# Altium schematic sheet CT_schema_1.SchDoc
size 604 x 452 mm
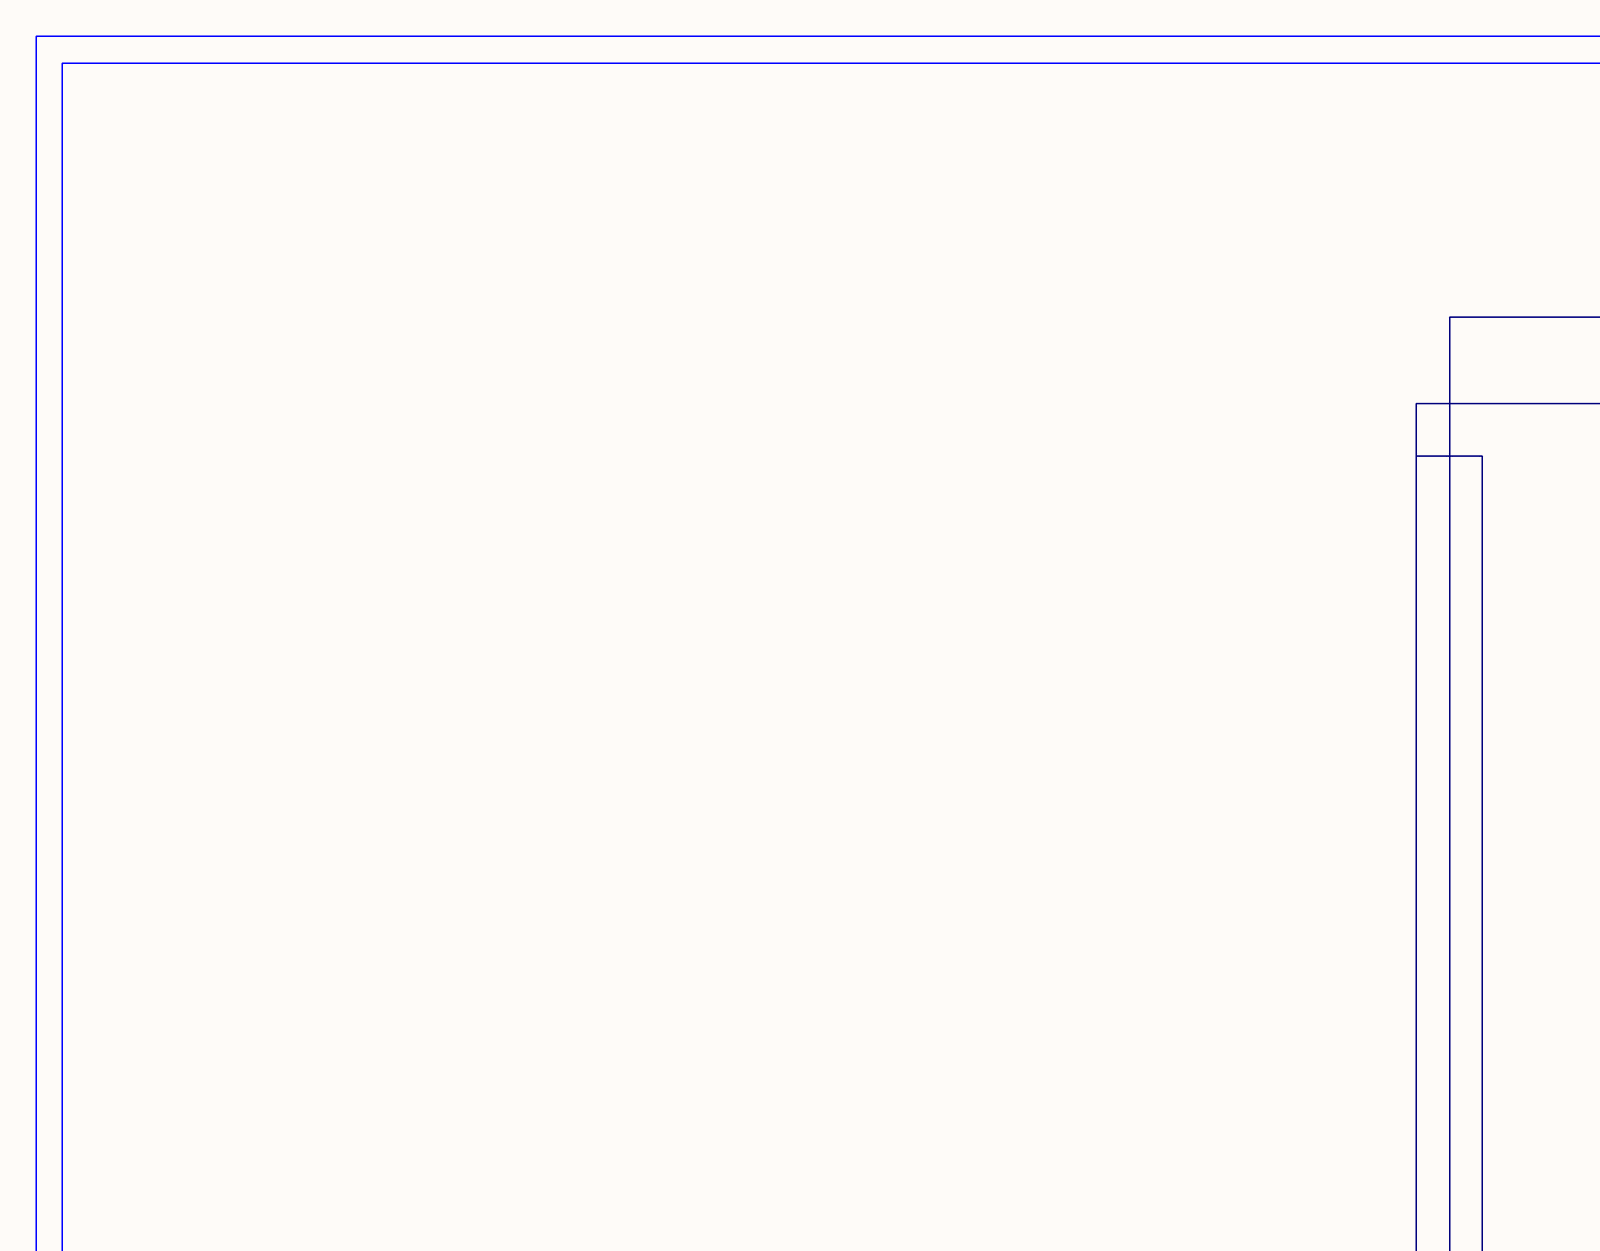
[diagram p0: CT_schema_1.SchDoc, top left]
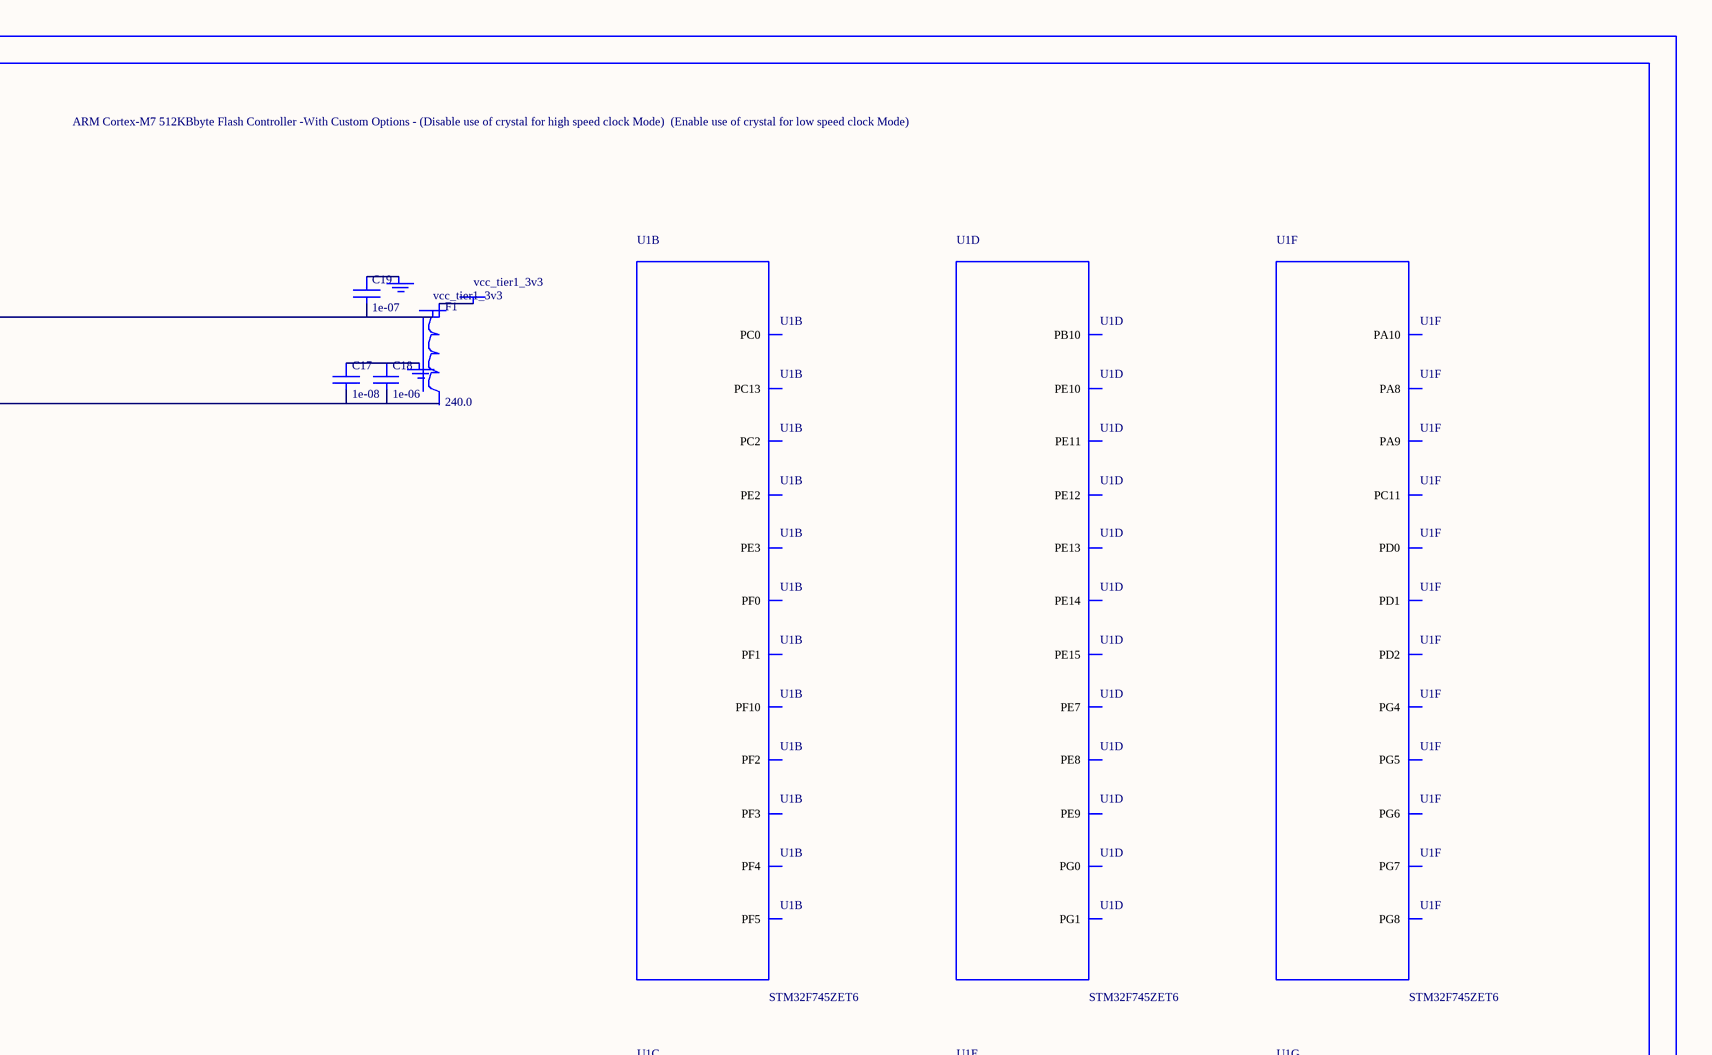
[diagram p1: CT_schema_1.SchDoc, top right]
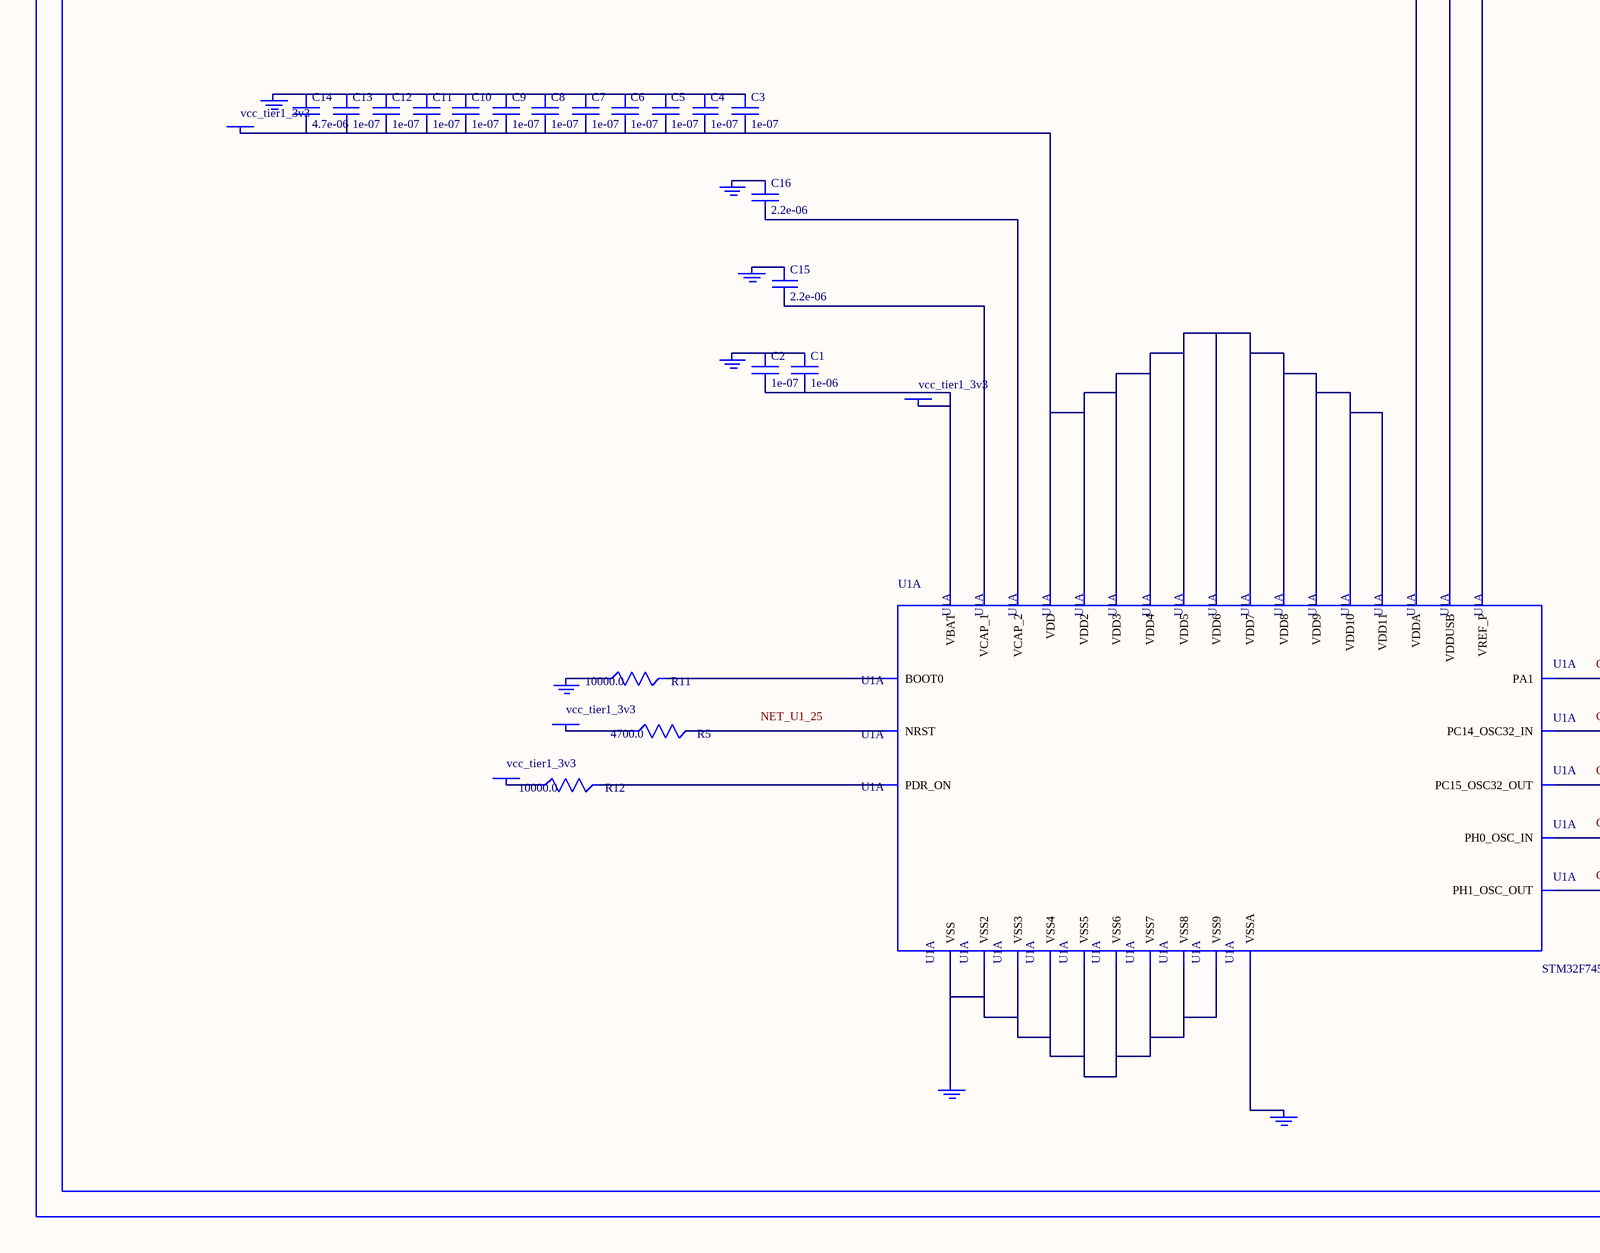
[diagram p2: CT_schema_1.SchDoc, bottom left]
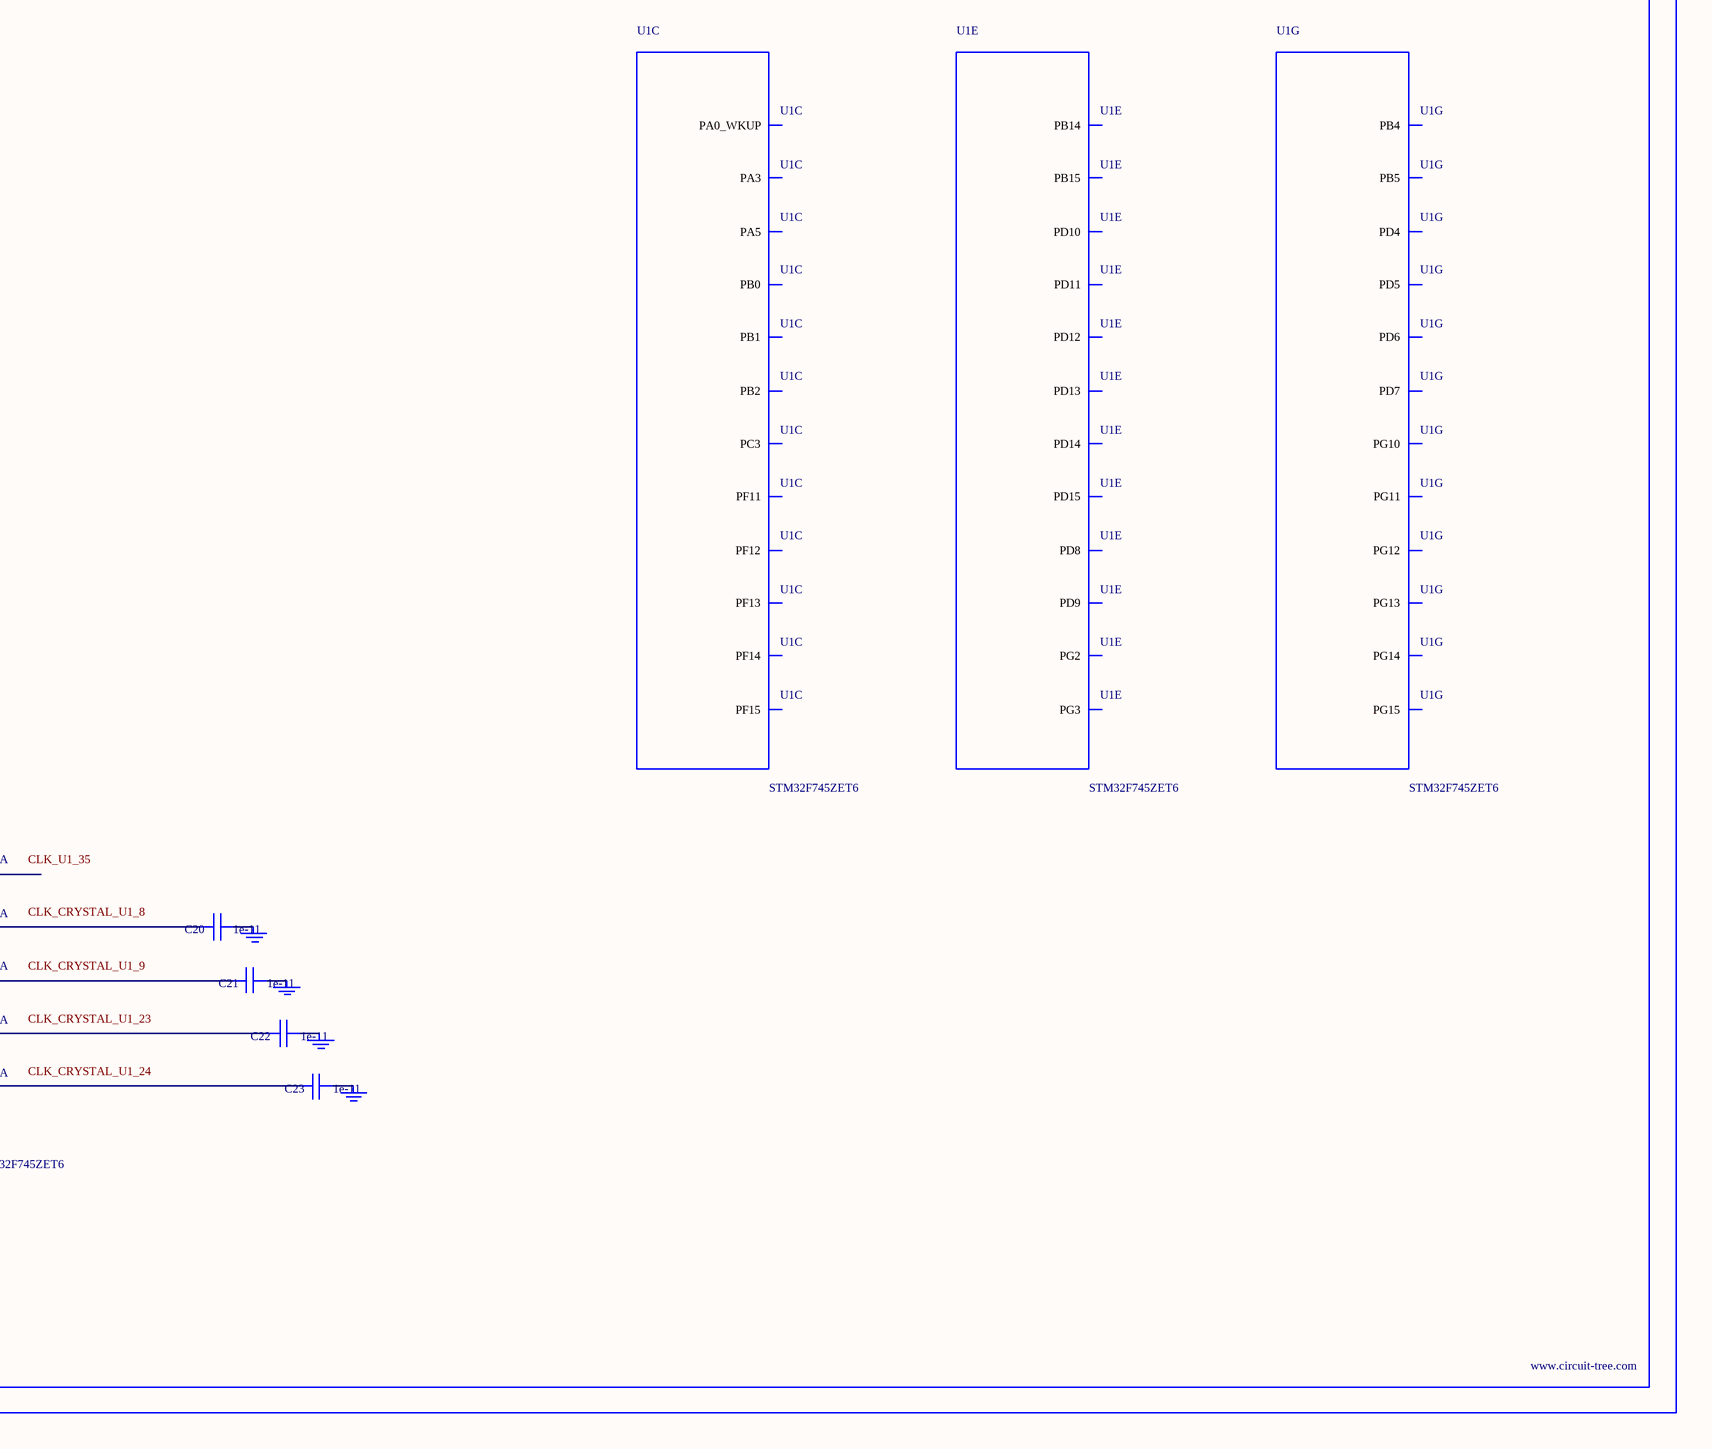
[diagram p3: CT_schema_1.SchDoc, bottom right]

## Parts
BORDER0  (no value)
C1  1e-06  [C0603]
C2  1e-07  [C0603]
C3  1e-07  [C0603]
C4  1e-07  [C0603]
C5  1e-07  [C0603]
C6  1e-07  [C0603]
C7  1e-07  [C0603]
C8  1e-07  [C0603]
C9  1e-07  [C0603]
C10  1e-07  [C0603]
C11  1e-07  [C0603]
C12  1e-07  [C0603]
C13  1e-07  [C0603]
C14  4.7e-06  [C0603]
C15  2.2e-06  [C0603]
C16  2.2e-06  [C0603]
C17  1e-08  [C0603]
C18  1e-06  [C0603]
C19  1e-07  [C0603]
C20  1e-11  [C0402]
C21  1e-11  [C0402]
C22  1e-11  [C0402]
C23  1e-11  [C0402]
F1  240.0  [L0603]
GND_INSTANCE_0_0  (no value)
GND_INSTANCE_0_1  (no value)
GND_INSTANCE_0_2  (no value)
GND_INSTANCE_0_3  (no value)
GND_INSTANCE_0_4  (no value)
GND_INSTANCE_0_5  (no value)
GND_INSTANCE_0_6  (no value)
GND_INSTANCE_0_7  (no value)
GND_INSTANCE_0_8  (no value)
GND_INSTANCE_0_9  (no value)
GND_INSTANCE_0_10  (no value)
GND_INSTANCE_0_11  (no value)
GND_INSTANCE_0_12  (no value)
POWER_INSTANCE_0_0  vcc_tier1_3v3
POWER_INSTANCE_0_1  vcc_tier1_3v3
POWER_INSTANCE_0_2  vcc_tier1_3v3
POWER_INSTANCE_0_3  vcc_tier1_3v3
POWER_INSTANCE_0_4  vcc_tier1_3v3
POWER_INSTANCE_0_5  vcc_tier1_3v3
R5  4700.0  [R0603]
R11  10000.0  [R0603]
R12  10000.0  [R0603]
U1  STM32F745ZET6  [LQFP144]  (parts A,B,C,D,E,F,G of 12)

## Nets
NetC1_1: C1.1 C2.1 GND_INSTANCE_0_0.0(GND)
NetC1_2: C1.2 C2.2 POWER_INSTANCE_0_0.0(PWR) U1.6(VBAT)
NetC3_1: C3.1 C4.1 C5.1 C6.1 C7.1 C8.1 C9.1 C10.1 C11.1 C12.1 C13.1 C14.1 GND_INSTANCE_0_3.0(GND)
NetC3_2: C3.2 C4.2 C5.2 C6.2 C7.2 C8.2 C9.2 C10.2 C11.2 C12.2 C13.2 C14.2 POWER_INSTANCE_0_1.0(PWR) U1.17(VDD) U1.30(VDD2) U1.39(VDD3) U1.52(VDD4) U1.62(VDD5) U1.72(VDD6) U1.84(VDD7) U1.108(VDD8) U1.121(VDD9) U1.131(VDD10) U1.144(VDD11)
NetC15_1: C15.1 GND_INSTANCE_0_8.0(GND)
NetC15_2: C15.2 U1.71(VCAP_1)
NetC16_1: C16.1 GND_INSTANCE_0_10.0(GND)
NetC16_2: C16.2 U1.106(VCAP_2)
NetC17_1: C17.1 C18.1 GND_INSTANCE_0_7.0(GND)
NetC17_2: C17.2 C18.2 U1.32(VREF_P) U1.33(VDDA)
NetC19_1: C19.1 GND_INSTANCE_0_9.0(GND)
NetC19_2: C19.2 POWER_INSTANCE_0_3.0(PWR) U1.95(VDDUSB)
NetC20_1: C20.1 GND_INSTANCE_0_1.0(GND)
NetC20_2: C20.2 U1.8(PC14_OSC32_IN)
NetC21_1: C21.1 GND_INSTANCE_0_2.0(GND)
NetC21_2: C21.2 U1.9(PC15_OSC32_OUT)
NetC22_1: C22.1 GND_INSTANCE_0_4.0(GND)
NetC22_2: C22.2 U1.23(PH0_OSC_IN)
NetC23_1: C23.1 GND_INSTANCE_0_5.0(GND)
NetC23_2: C23.2 U1.24(PH1_OSC_OUT)
NetF1_1: F1.1 POWER_INSTANCE_0_2.0(PWR)
NetGND_INSTANCE_0_6_0: GND_INSTANCE_0_6.0(GND) U1.31(VSSA)
NetGND_INSTANCE_0_11_0: GND_INSTANCE_0_11.0(GND) R11.1
NetGND_INSTANCE_0_12_0: GND_INSTANCE_0_12.0(GND) U1.16(VSS) U1.38(VSS2) U1.51(VSS3) U1.61(VSS4) U1.83(VSS5) U1.94(VSS6) U1.107(VSS7) U1.120(VSS8) U1.130(VSS9)
NetPOWER_INSTANCE_0_4_0: POWER_INSTANCE_0_4.0(PWR) R12.1
NetPOWER_INSTANCE_0_5_0: POWER_INSTANCE_0_5.0(PWR) R5.1
NetR5_2: R5.2 U1.25(NRST)
NetR11_2: R11.2 U1.138(BOOT0)
NetR12_2: R12.2 U1.143(PDR_ON)

Not connected (* = marked no-connect by the designer): F1 2; U1 1(PE2) 2(PE3) 7(PC13) 10(PF0) 11(PF1) 12(PF2) 13(PF3) 14(PF4) 15(PF5) 22(PF10) 26(PC0) 28(PC2) 29(PC3) 34(PA0_WKUP) 35(PA1) 37(PA3) 41(PA5) 46(PB0) 47(PB1) 48(PB2) 49(PF11) 50(PF12) 53(PF13) 54(PF14) 55(PF15) 56(PG0) 57(PG1) 58(PE7) 59(PE8) 60(PE9) 63(PE10) 64(PE11) 65(PE12) 66(PE13) 67(PE14) 68(PE15) 69(PB10) 75(PB14) 76(PB15) 77(PD8) 78(PD9) 79(PD10) 80(PD11) 81(PD12) 82(PD13) 85(PD14) 86(PD15) 87(PG2) 88(PG3) 89(PG4) 90(PG5) 91(PG6) 92(PG7) 93(PG8) 100(PA8) 101(PA9) 102(PA10) 112(PC11) 114(PD0) 115(PD1) 116(PD2) 118(PD4) 119(PD5) 122(PD6) 123(PD7) 125(PG10) 126(PG11) 127(PG12) 128(PG13) 129(PG14) 132(PG15) 134(PB4) 135(PB5)

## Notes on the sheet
- Labels drawn without touching a wire or pin: CLK_CRYSTAL_U1_8, CLK_CRYSTAL_U1_9, CLK_CRYSTAL_U1_23, CLK_CRYSTAL_U1_24, CLK_U1_35, NET_U1_25

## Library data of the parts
BORDER0 = BORDER_PAGE0
C1 C18 = C0603C105K3RACTU
C2-C13 C19 = 06035C104K4Z2A
C14 = GRM188R6YA475KE15D
C15 C16 = C0603C225K8RACTU
C17 = 06035C103K4Z2A
C20-C23 = C0402C100K3GACTU
F1 = Z0603C241ASMST
GND_INSTANCE_0_0-GND_INSTANCE_0_12 = GND
POWER_INSTANCE_0_0-POWER_INSTANCE_0_5 = PWR
R5 = RC0603JR-074K7L
R11 R12 = RC0603JR-0710KL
